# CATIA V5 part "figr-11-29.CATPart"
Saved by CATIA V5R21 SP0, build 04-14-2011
Part number: Part1
Bounding box of the stored display mesh (mm): x -52 to 53, y -75.374 to 75.374, z 0 to 37.54
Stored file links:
  D:\CATIA V5R21 E-RESOURCES\CATIA-V5R21\catia-v5r21-prt\c11-catia-v5r21-prt\c11-catia-v5r21-figr-11-29.CATPart
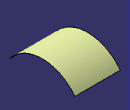
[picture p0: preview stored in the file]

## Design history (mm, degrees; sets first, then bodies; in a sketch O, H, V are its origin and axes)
Set1
  Extrude1: Element1 Sketch1, Lim1 53, Lim2 52, Direction yz-plane
Body1 (main body)
  Sketch1 on yz-plane, origin (0, 0, 0), H (0, 1, 0), V (0, 0, 1)
    arc A1 centre (0, -56.4477) radius 94.1675 from (-75.3736, 0) to (75.3736, 0) cw
    point P1 (0, -56.4477)
    point P2 (-75.3736, 0)
    point P3 (75.3736, 0)
    point P4 (0, 37.7198)
    coincidence: P2 H, P3 H, A1 P4, P4 V, P1 V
